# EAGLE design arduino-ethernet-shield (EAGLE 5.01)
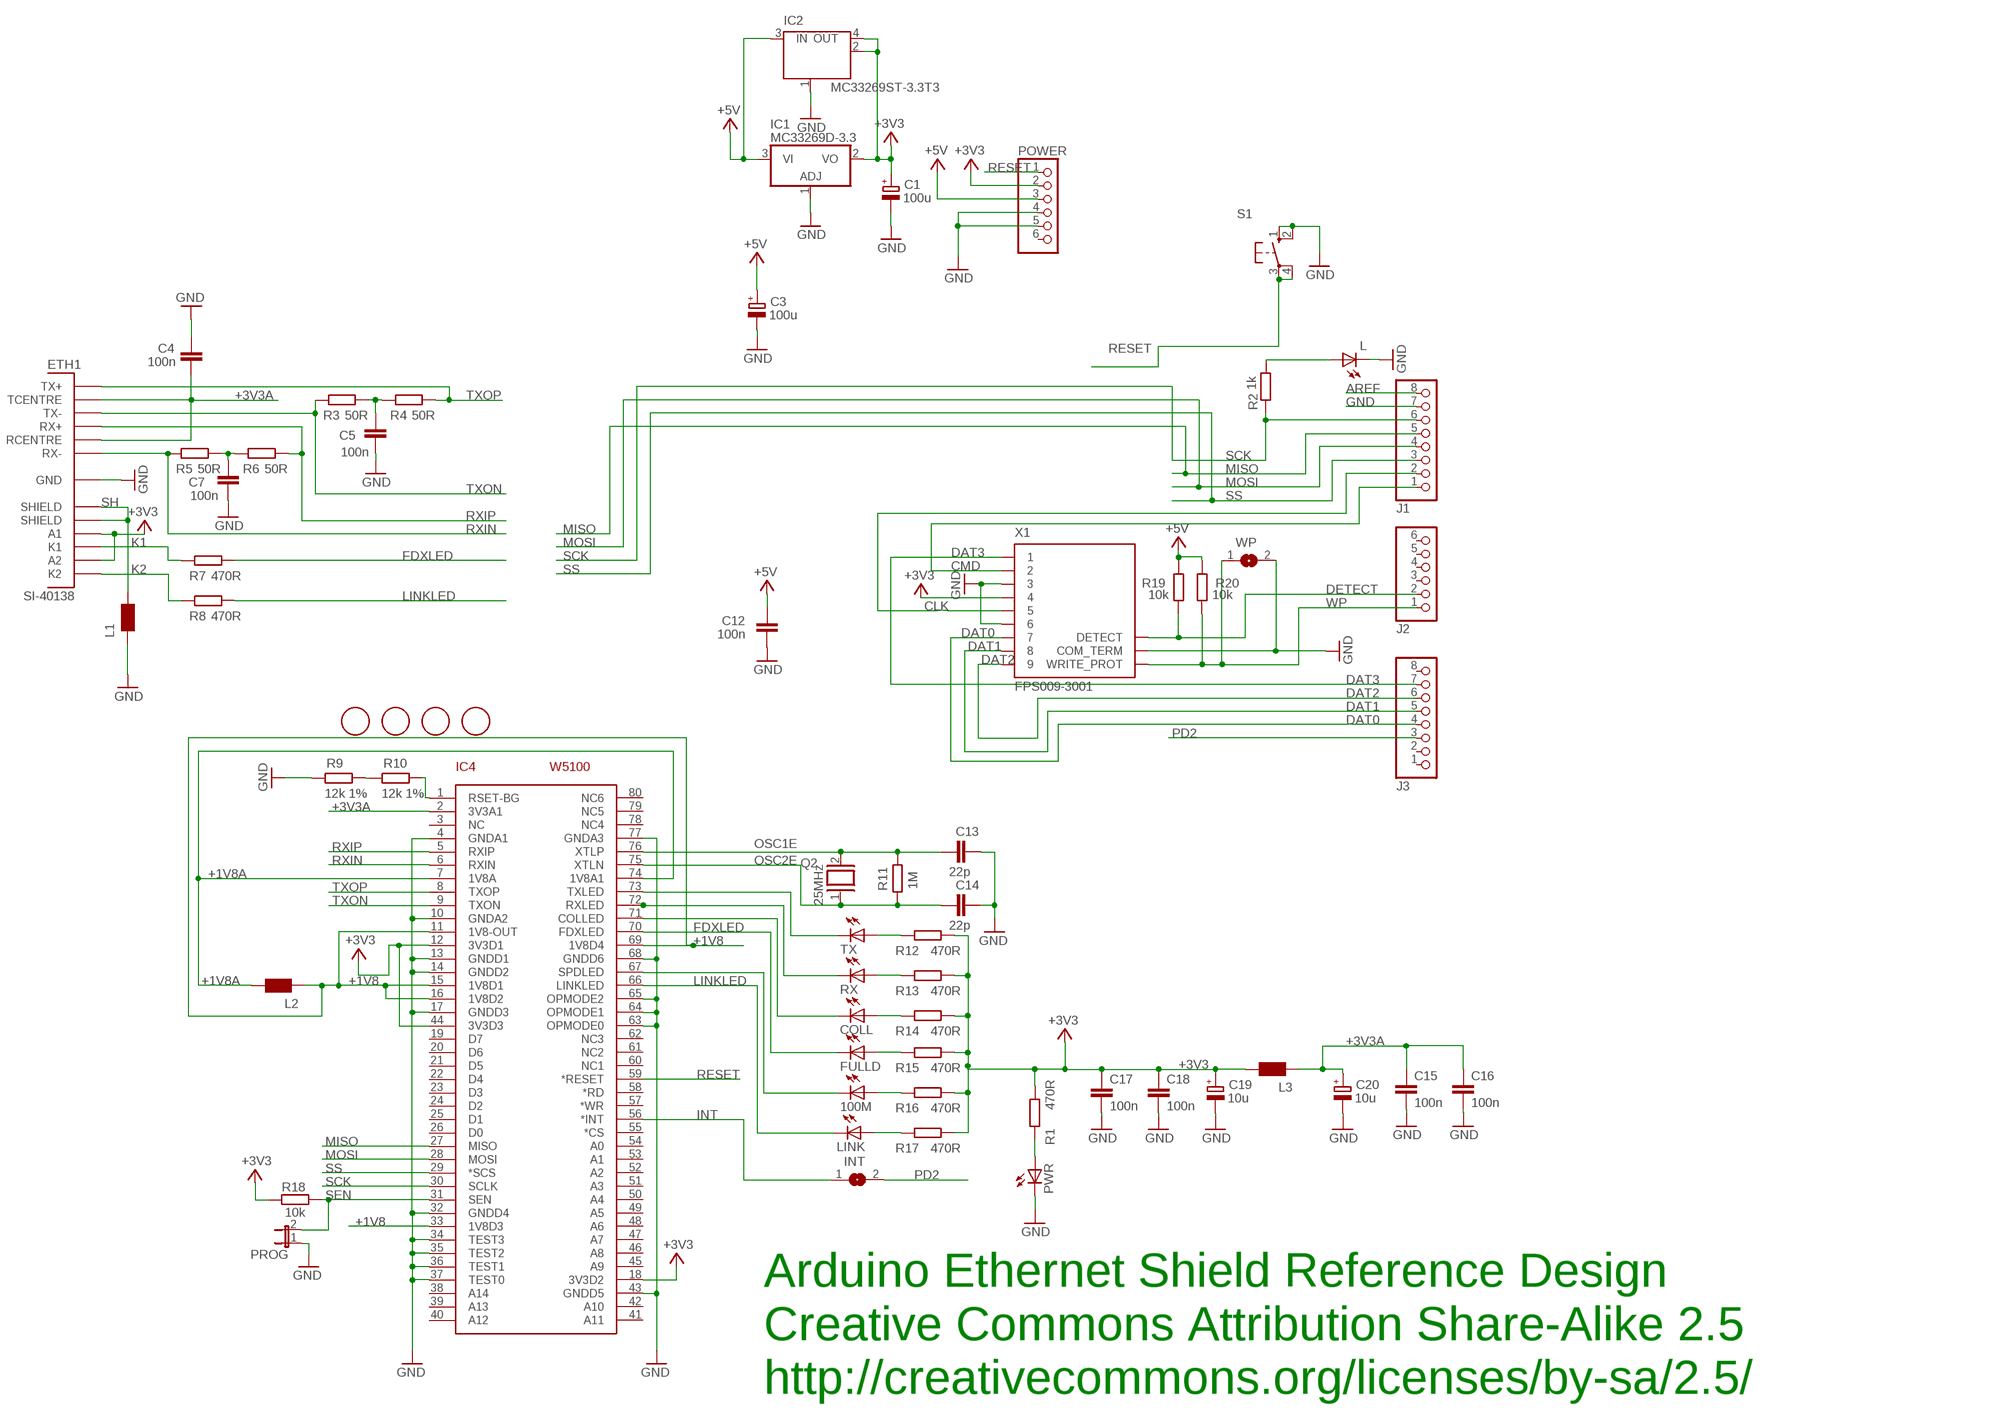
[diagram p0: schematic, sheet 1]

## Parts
100M  LEDCHIPLED_0805  [CHIPLED_0805]
C1  100u  CPOL-EUSMCD  [SMC_D]
C3  100u  CPOL-EUSMCD  [SMC_D]
C4  100n  C-EU  [0805RND]
C5  100n  C-EU  [0805RND]
C7  100n  C-EU  [0805RND]
C12  100n  C-EU  [0805RND]
C13  22p  C-EU  [0805RND]
C14  22p  C-EU  [0805RND]
C15  100n  C-EU  [0805RND]
C16  100n  C-EU  [0805RND]
C17  100n  C-EU  [0805RND]
C18  100n  C-EU  [0805RND]
C19  10u  CPOL-EUSMCB  [SMC_B]
C20  10u  CPOL-EUSMCB  [SMC_B]
COLL  LEDCHIPLED_0805  [CHIPLED_0805]
ETH1  SI-40138  [SI40138]
F1  FIDUCIALMOUNT  [FIDUCIA-MOUNT]
F2  FIDUCIALMOUNT  [FIDUCIA-MOUNT]
F3  FIDUCIALMOUNT  [FIDUCIA-MOUNT]
F4  FIDUCIALMOUNT  [FIDUCIA-MOUNT]
FULLD  LEDCHIPLED_0805  [CHIPLED_0805]
IC1  MC33269D-3.3  [DPACK]
IC2  MC33269ST-3.3T3  [SOT223]
IC4  W5100  [SQFP-S-10X10-80]
INT  SJ  [SJ]
J1  PINHD-1X8  [1X08]
J2  PINHD-1X6  [1X06]
J3  PINHD-1X8  [1X08]
L  LEDCHIPLED_0805  [CHIPLED_0805]
L1  WE-CBF_0805  [0805]
L2  WE-CBF_0805  [0805]
L3  WE-CBF_0805  [0805]
LINK  LEDCHIPLED_0805  [CHIPLED_0805]
POWER  PINHD-1X6  [1X06]
PROG  JP1E  [JP1]
PWR  LEDCHIPLED_0805  [CHIPLED_0805]
Q2  25MHz  XTAL/S  [QS]
R1  470R  R-EU_  [0805RND]
R2  1k  R-EU_  [0805RND]
R3  50R  R-EU_  [0805RND]
R4  50R  R-EU_  [0805RND]
R5  50R  R-EU_  [0805RND]
R6  50R  R-EU_  [0805RND]
R7  470R  R-EU_  [0805RND]
R8  470R  R-EU_  [0805RND]
R9  12k 1%  R-EU_  [0805RND]
R10  12k 1%  R-EU_  [0805RND]
R11  1M  R-EU_  [0805RND]
R12  470R  R-EU_  [0805RND]
R13  470R  R-EU_  [0805RND]
R14  470R  R-EU_  [0805RND]
R15  470R  R-EU_  [0805RND]
R16  470R  R-EU_  [0805RND]
R17  470R  R-EU_  [0805RND]
R18  10k  R-EU_  [0805RND]
R19  10k  R-EU_  [0805RND]
R20  10k  R-EU_  [0805RND]
RX  LEDCHIPLED_0805  [CHIPLED_0805]
S1  10-XX  [B3F-10XX]
TX  LEDCHIPLED_0805  [CHIPLED_0805]
WP  SJ  [SJ]
X1  FPS009-3001  [FPS009-3000]

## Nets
+1V8 [power]: IC4.11(1V8-OUT) IC4.15(1V8D1) IC4.16(1V8D2) IC4.33(1V8D3) IC4.69(1V8D4) L2.1
+1V8A [power]: IC4.7(1V8A) IC4.74(1V8A1) L2.2
+3V3 [power]: C1.+ C17.P$1 C18.P$1 C19.+ ETH1.9(A1) ETH1.11(A2) IC1.2(VO) IC2.2(OUT) IC2.4(OUT) IC4.12(3V3D1) IC4.18(3V3D2) IC4.44(3V3D3) L3.2 POWER.2 R1.P$1 R12.P$1 R13.P$1 R14.P$1 R15.P$1 R16.P$1 R17.P$1 R18.P$1 X1.4
+3V3A [power]: C4.P$1 C15.P$1 C16.P$1 C20.+ ETH1.2(TCENTRE) ETH1.5(RCENTRE) IC4.2(3V3A1) L3.1
+5V [power]: C3.+ C12.P$1 IC1.3(VI) IC2.3(IN) POWER.3 R19.P$2 R20.P$2
AREF: J1.8
CLK: J1.2 X1.5
CMD: J1.1 X1.2
DAT0: J3.4 X1.7
DAT1: J3.5 X1.8
DAT2: J3.6 X1.9
DAT3: J3.7 X1.1
DETECT: J2.2 R19.P$1 X1.DETECT
FDXLED: FULLD.C IC4.70(FDXLED) R7.P$1
GND [power]: C1.- C3.- C4.P$2 C5.P$1 C7.P$1 C12.P$2 C13.P$1 C14.P$1 C15.P$2 C16.P$2 C17.P$2 C18.P$2 C19.- C20.- ETH1.8(GND) IC1.1(ADJ) IC2.1(GND/ADJ) IC4.4(GNDA1) IC4.10(GNDA2) IC4.13(GNDD1) IC4.14(GNDD2) IC4.17(GNDD3) IC4.32(GNDD4) IC4.34(TEST3) IC4.35(TEST2) IC4.36(TEST1) IC4.37(TEST0) IC4.43(GNDD5) IC4.63(OPMODE0) IC4.64(OPMODE1) IC4.65(OPMODE2) IC4.68(GNDD6) IC4.77(GNDA3) J1.7 L1.1 L.C POWER.4 POWER.5 PROG.1 PWR.C R9.P$2 S1.1(S) S1.2(S1) WP.2 X1.3 X1.6 X1.COM_TERM
INT: IC4.56(*INT) INT.1
K1: ETH1.10(K1) R7.P$2
K2: ETH1.12(K2) R8.P$2
LINKLED: IC4.66(LINKLED) LINK.C R8.P$1
MISO: IC4.27(MISO) J1.5
MOSI: IC4.28(MOSI) J1.4
N$1: PWR.A R1.P$2
N$2: L.A R2.P$1
N$5: 100M.C IC4.67(SPDLED)
N$6: IC4.73(TXLED) TX.C
N$7: IC4.72(RXLED) RX.C
N$8: COLL.C IC4.71(COLLED)
N$9: R12.P$2 TX.A
N$10: C5.P$2 R3.P$1 R4.P$2
N$22: R13.P$2 RX.A
N$23: COLL.A R14.P$2
N$24: FULLD.A R15.P$2
N$25: 100M.A R16.P$2
N$26: LINK.A R17.P$2
N$29: C7.P$2 R5.P$1 R6.P$2
N$30: R9.P$1 R10.P$2
N$31: IC4.1(RSET-BG) R10.P$1
OSC1E: C13.P$2 IC4.76(XTLP) Q2.2 R11.P$1
OSC2E: C14.P$2 IC4.75(XTLN) Q2.1 R11.P$2
PD2: INT.2 J3.3
RESET: IC4.59(*RESET) POWER.1 S1.3(P) S1.4(P1)
RXIN: ETH1.6(RX-) IC4.6(RXIN) R5.P$2
RXIP: ETH1.4(RX+) IC4.5(RXIP) R6.P$1
SCK: IC4.30(SCLK) J1.6 R2.P$2
SEN: IC4.31(SEN) PROG.2 R18.P$2
SH: ETH1.S1(SHIELD) ETH1.S2(SHIELD) L1.2
SS: IC4.29(*SCS) J1.3
TXON: ETH1.3(TX-) IC4.9(TXON) R3.P$2
TXOP: ETH1.1(TX+) IC4.8(TXOP) R4.P$1
WP: J2.1 R20.P$1 WP.1 X1.WRITE_PROT
Unconnected: IC4.3(NC) IC4.19(D7) IC4.20(D6) IC4.21(D5) IC4.22(D4) IC4.23(D3) IC4.24(D2) IC4.25(D1) IC4.26(D0) IC4.38(A14) IC4.39(A13) IC4.40(A12) IC4.41(A11) IC4.42(A10) IC4.45(A9) IC4.46(A8) IC4.47(A7) IC4.48(A6) IC4.49(A5) IC4.50(A4) IC4.51(A3) IC4.52(A2) IC4.53(A1) IC4.54(A0) IC4.55(*CS) IC4.57(*WR) IC4.58(*RD) IC4.60(NC1) IC4.61(NC2) IC4.62(NC3) IC4.78(NC4) IC4.79(NC5) IC4.80(NC6) J2.3 J2.4 J2.5 J2.6 J3.1 J3.2 J3.8 POWER.6

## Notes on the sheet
- Arduino Ethernet Shield Reference Design
- Creative Commons Attribution Share-Alike 2.5
- http://creativecommons.org/licenses/by-sa/2.5/

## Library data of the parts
100M COLL FULLD L LINK PWR RX TX = led:LED: LED
C1 C3 C19 C20 = rcl:CPOL-EU: POLARIZED CAPACITOR, European symbol
C4 C5 C7 C12-C18 = rcl:C-EU: CAPACITOR, European symbol
ETH1 = ethernet:SI-40138: Ethernet Jack with Integrated Magnetics The Belfuse SI-10021 (Rapid order code 24-0484) is a single RJ-45 jack with integrated magnetics, suitable for Ethernet use.
F1-F4 = SmartPrj:FIDUCIALMOUNT
IC1 = linear:MC33269?*: Adjustable Output Low Dropout Voltage Regulator 800 mA Source: http://www.onsemi.com/pub/Collateral/MC33269-D.PDF
IC2 = linear:MC33269ST*: Adjustable Output Low Dropout Voltage Regulator 800 mA Source: http://www.onsemi.com/pub/Collateral/MC33269-D.PDF
IC4 = SmartPrj:W5100
INT WP = jumper:SJ: SMD solder JUMPER
J1 J3 = pinhead:PINHD-1X8: PIN HEADER
J2 POWER = pinhead:PINHD-1X6: PIN HEADER
L1-L3 = wuerth-elektronik:WE-CBF: SMD EMI Suppression Ferrite Beads
PROG = jumper:JP1E: JUMPER
Q2 = special:XTAL/S: CRYSTAL
R1-R20 = rcl:R-EU_: RESISTOR, European symbol
S1 = switch-omron:10-XX: OMRON SWITCH
X1 = con-yamaichi:FPS009-300*: SD Card and MMC Reader (Manual Insertion) Source: http://www.yamaichi.de/pdf/c_fps009_3000.pdf

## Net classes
0 default: width 0.152 mm, drill 0.61 mm, clearance 0.152 mm
1 power: width 0.152 mm, drill 0.61 mm, clearance 0.152 mm
2 VIN: width 0.61 mm, drill 0.813 mm

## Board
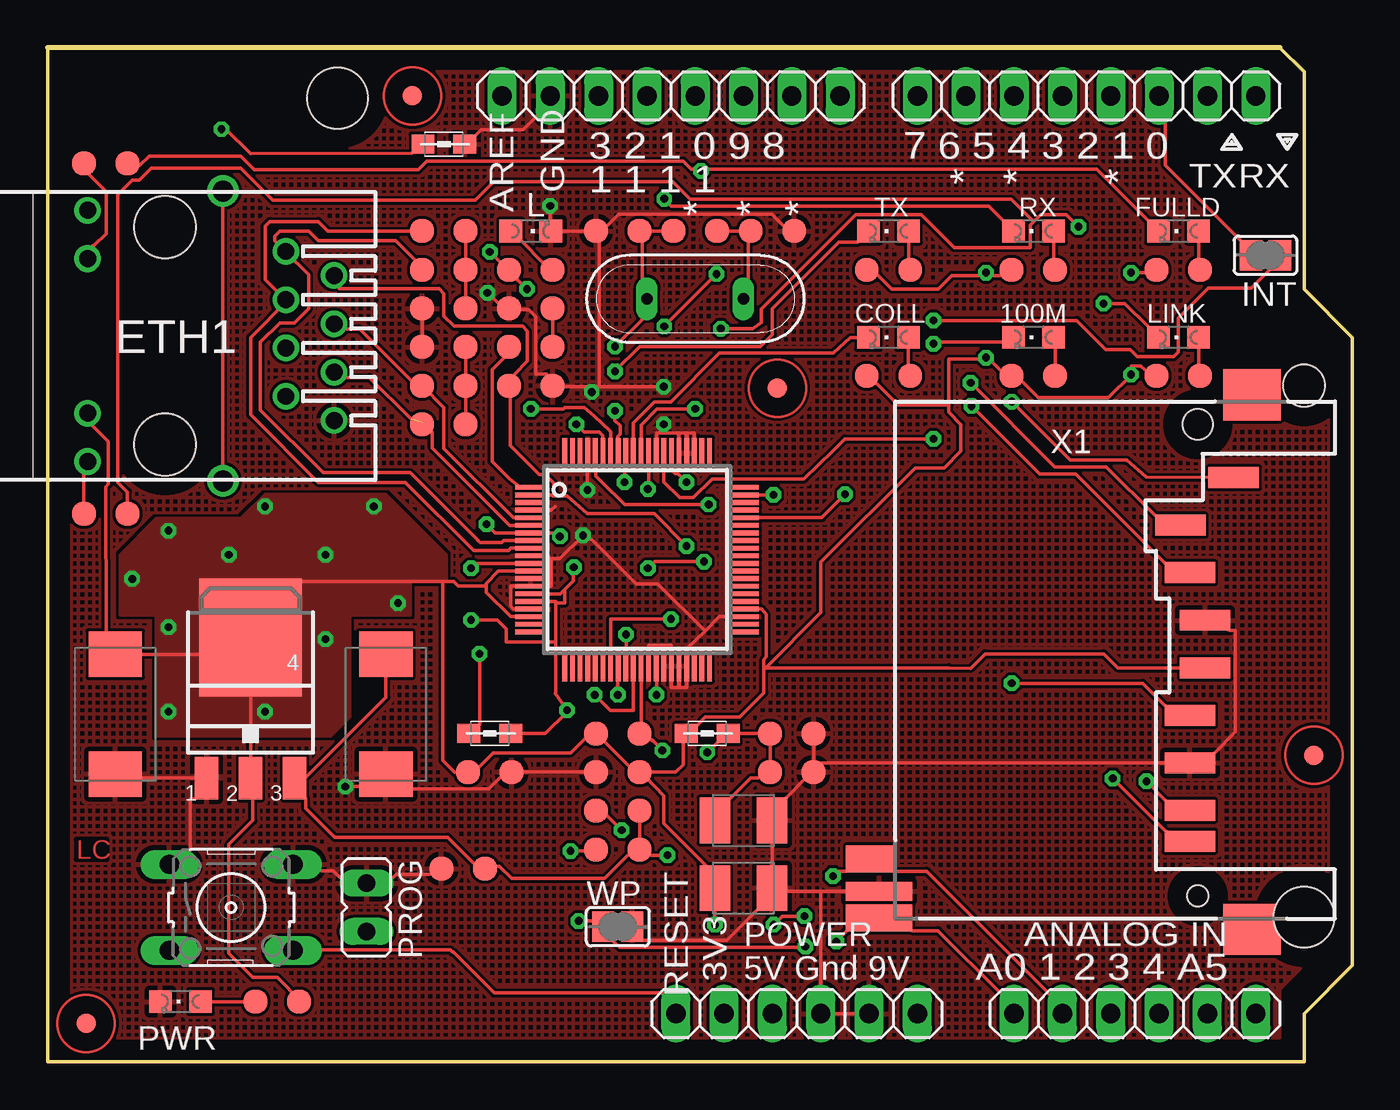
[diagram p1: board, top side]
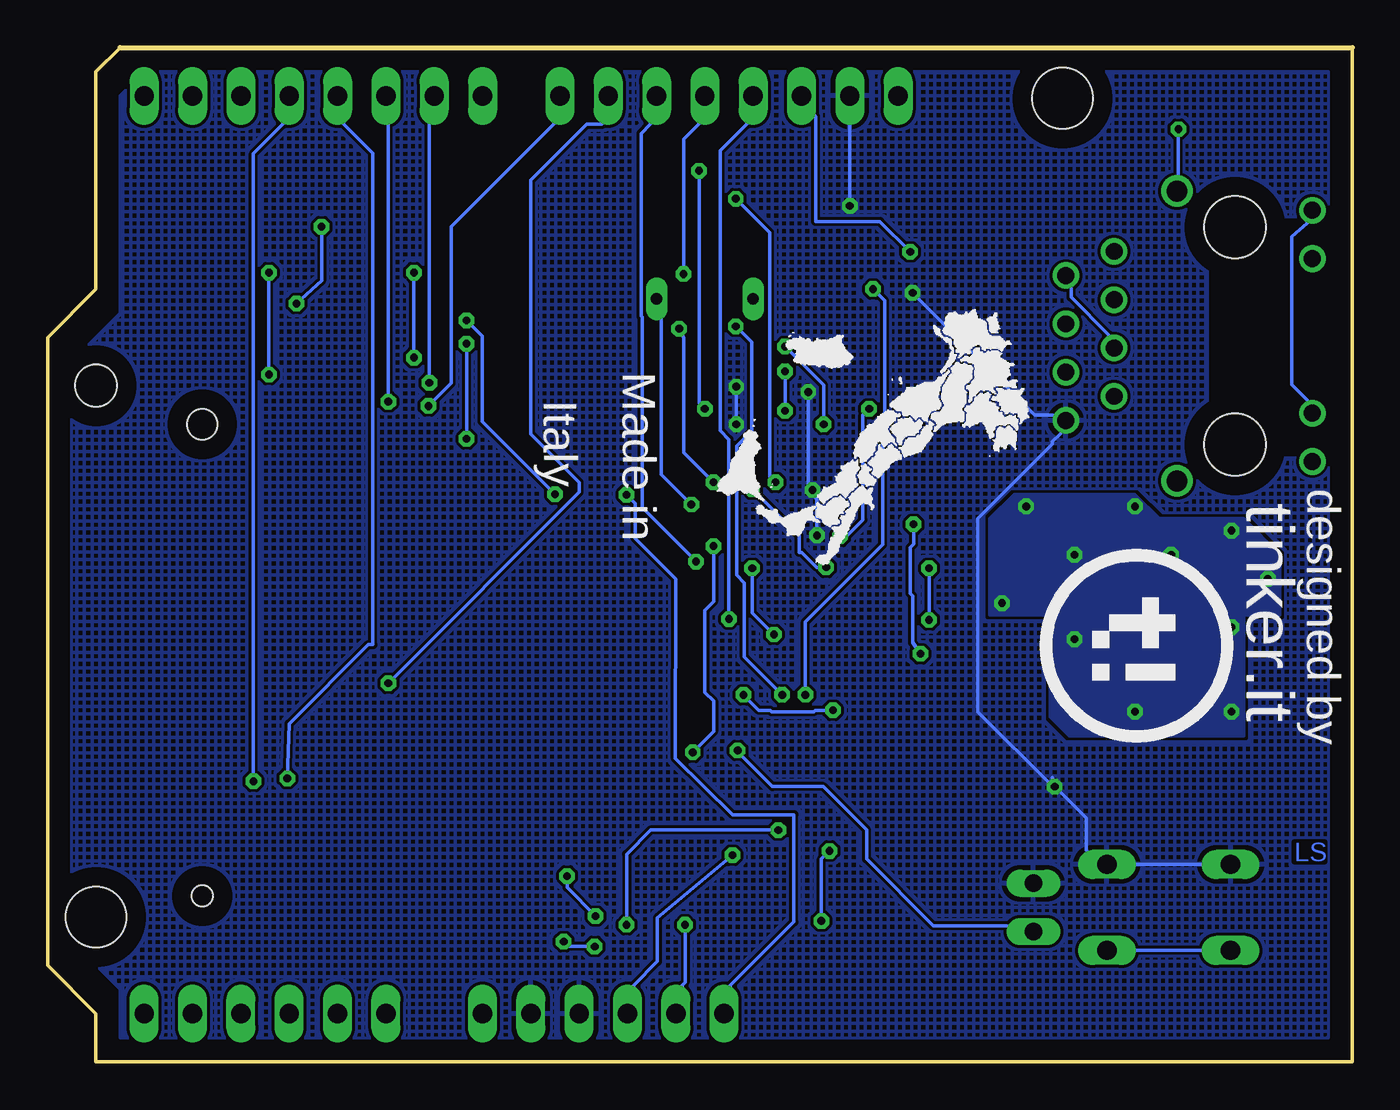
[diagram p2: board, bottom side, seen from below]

Size 68.58 x 53.34 mm. Coordinates in mm from the lower left corner, seen from the top.
Outline: 0,53.34 0,0 66.04,0 66.04,2.54 68.58,5.08 68.58,38.1 66.04,40.64 66.04,52.07 64.77,53.34 0,53.34
Copper layers (1*16): Top 0.035mm / dielectric 1.5mm / Bottom 0.035mm
Design rules "default *": minimum track width 8mil, minimum drill 20mil, track to track 6mil, track to pad 6mil, pad to pad 5mil, via to via 8mil, smd to smd 6mil, copper to edge 40mil, drill to drill 10mil, minimum pad ring 10mil, minimum via ring 8mil, stop-mask expansion 4mil, vias tented up to drill 0mil, thermal gap 10mil
Holes 2.2 mm at 66.04,35.56
Holes 3.2 mm at 66.04,7.62 15.24,50.67

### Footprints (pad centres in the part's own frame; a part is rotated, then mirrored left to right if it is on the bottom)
CHIPLED_0805 = smd 1.2 x 1.2: A 0,-1.05; C 0,1.05
SMC_D = smd 2.4 x 2.8: + -3.15,0; - 3.15,0
0805RND = smd 1.27 x 1.27: P$1 -1.143,0; P$2 1.143,0
SMC_B = smd 1.6 x 2.4: + -1.5,0; - 1.5,0
SI40138 = drill 0.889 round: 1 -4.445,6.35; 2 -3.175,8.89; 3 -1.905,6.35; 4 -0.635,8.89; 5 0.635,6.35; 6 1.905,8.89; 7 3.175,6.35; 8 4.445,8.89; 9 -6.604,-4.064; 10 -4.064,-4.064; 11 4.064,-4.064; 12 6.604,-4.064 | drill 1.1 round: S1 -7.62,3.048; S2 7.62,3.048 | hole 3.251: -5.715,0; 5.715,0
FIDUCIA-MOUNT = smd 1.016 x 1.016: P$1 0,0
DPACK = smd 1 x 1.6: 1 -2.28,-4.8; 3 2.28,-4.8 | smd 5.4 x 6.2: 2 0,2.5
SOT223 = smd 1.219 x 2.235: 1 -2.311,-3.099; 2 0,-3.099; 3 2.311,-3.099 | smd 3.6 x 2.2: 4 0,3.099
SQFP-S-10X10-80 = smd 0.25 x 1.6: 1 -3.8,-5.6; 2 -3.4,-5.6; 3 -3,-5.6; 4 -2.6,-5.6; 5 -2.2,-5.6; 6 -1.8,-5.6; 7 -1.4,-5.6; 8 -1,-5.6; 9 -0.6,-5.6; 10 -0.2,-5.6; 11 0.2,-5.6; 12 0.6,-5.6; 13 1,-5.6; 14 1.4,-5.6; 15 1.8,-5.6; 16 2.2,-5.6; 17 2.6,-5.6; 18 3,-5.6; 19 3.4,-5.6; 20 3.8,-5.6; 41 3.8,5.6; 42 3.4,5.6; 43 3,5.6; 44 2.6,5.6; 45 2.2,5.6; 46 1.8,5.6; 47 1.4,5.6; 48 1,5.6; 49 0.6,5.6; 50 0.2,5.6; 51 -0.2,5.6; 52 -0.6,5.6; 53 -1,5.6; 54 -1.4,5.6; 55 -1.8,5.6; 56 -2.2,5.6; 57 -2.6,5.6; 58 -3,5.6; 59 -3.4,5.6; 60 -3.8,5.6 | smd 1.6 x 0.25: 21 5.6,-3.8; 22 5.6,-3.4; 23 5.6,-3; 24 5.6,-2.6; 25 5.6,-2.2; 26 5.6,-1.8; 27 5.6,-1.4; 28 5.6,-1; 29 5.6,-0.6; 30 5.6,-0.2; 31 5.6,0.2; 32 5.6,0.6; 33 5.6,1; 34 5.6,1.4; 35 5.6,1.8; 36 5.6,2.2; 37 5.6,2.6; 38 5.6,3; 39 5.6,3.4; 40 5.6,3.8; 61 -5.6,3.8; 62 -5.6,3.4; 63 -5.6,3; 64 -5.6,2.6; 65 -5.6,2.2; 66 -5.6,1.8; 67 -5.6,1.4; 68 -5.6,1; 69 -5.6,0.6; 70 -5.6,0.2; 71 -5.6,-0.2; 72 -5.6,-0.6; 73 -5.6,-1; 74 -5.6,-1.4; 75 -5.6,-1.8; 76 -5.6,-2.2; 77 -5.6,-2.6; 78 -5.6,-3; 79 -5.6,-3.4; 80 -5.6,-3.8
SJ = smd 1.168 x 1.6: 1 -0.762,0; 2 0.762,0
1X08 = drill 1.016 long: 1 -8.89,0; 2 -6.35,0; 3 -3.81,0; 4 -1.27,0; 5 1.27,0; 6 3.81,0; 7 6.35,0; 8 8.89,0
1X06 = drill 1.016 long: 1 -6.35,0; 2 -3.81,0; 3 -1.27,0; 4 1.27,0; 5 3.81,0; 6 6.35,0
0805 = smd 1.2 x 1: 1 -1.1,0; 2 1.1,0
JP1 = drill 0.914 long: 1 0,-1.27; 2 0,1.27
QS = drill 0.61 long: 1 -2.54,0; 2 2.54,0
B3F-10XX = drill 1.016 long: 1 -3.251,2.261; 2 3.251,2.261; 3 -3.251,-2.261; 4 3.251,-2.261
FPS009-3000 = smd 2.65 x 1.1: 1 -0.915,-5.3; 2 -0.415,-7.8; 3 0.385,-10.3; 4 0.385,-12.8; 5 -0.415,-15.3; 6 -0.415,-17.8; 7 -0.415,-20.3; 8 -0.415,-21.925; 9 1.885,-2.8 | smd 3.5 x 1: COM_TERM -16.75,-24.55 | smd 2.5 x 1.4: DETECT -17.25,-22.85 | smd 3 x 2.7: M1 2.85,1.55; M2 2.85,-26.55 | smd 3.5 x 1.4: WRITE_PROT -16.75,-25.95 | hole 1.6: 0,0 | hole 1.1: 0,-24.8

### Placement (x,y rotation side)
100M  51.82,38.1 90 top
C1  3.56,18.29 270 top
C3  17.78,18.29 270 top
C4  25.4,35.56 0 top
C5  20.83,39.62 0 top
C7  20.83,37.59 0 top
C12  21.84,10.16 180 top
C13  38.1,43.69 180 top
C14  29.97,43.69 0 top
C15  39.12,15.24 0 top
C16  39.12,17.27 0 top
C17  23.24,15.24 0 top
C18  29.97,15.24 180 top
C19  36.58,9.14 0 top
C20  36.58,12.7 0 top
COLL  44.2,38.1 90 top
ETH1  6.17,38.17 270 top
F1  38.35,35.43 0 top
F2  66.55,16.13 0 top
F3  19.18,50.8 0 top
F4  2.03,2.03 0 top
FULLD  59.44,43.69 90 top
IC1  10.67,19.81 0 top
IC2  10.67,18.03 0 top
IC4  30.99,26.42 270 top
INT  64.01,42.42 180 top
J1  32.77,50.8 180 top
J2  57.15,2.54 0 top
J3  54.61,50.8 180 top
L  25.4,43.69 270 top
L1  20.83,48.26 180 top
L2  23.24,17.27 180 top
L3  34.67,17.27 180 top
LINK  59.44,38.1 90 top
POWER  39.37,2.54 0 top
PROG  16.76,8.13 180 top
PWR  6.99,3.17 90 top
Q2  34.04,40.13 0 top
R1  12.06,3.17 180 top
R2  25.4,41.66 180 top
R3  20.83,43.69 180 top
R4  20.83,41.66 0 top
R5  20.83,33.53 180 top
R6  20.83,35.56 0 top
R7  3.05,47.24 180 top
R8  3.05,28.83 180 top
R9  25.4,39.62 180 top
R10  25.4,37.59 0 top
R11  34.04,43.69 180 top
R12  44.2,41.66 0 top
R13  51.82,41.66 0 top
R14  44.2,36.07 0 top
R15  59.44,41.66 0 top
R16  51.82,36.07 0 top
R17  59.44,36.07 0 top
R18  29.97,17.27 0 top
R19  29.97,13.21 0 top
R20  29.97,11.18 0 top
RX  51.82,43.69 90 top
S1  9.65,8.13 0 top
TX  44.2,43.69 90 top
WP  29.97,7.11 0 top
X1  60.45,33.53 0 top

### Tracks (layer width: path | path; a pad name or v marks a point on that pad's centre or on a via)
+1V8  (via drill 0.41)
  Top 0.178: 26.72,22.1 26.72,24.13 | 26.72,24.13 26.72,24.21 26.19,24.21 IC4.16 | 26.72,22.1 26.72,19.43 26.67,19.38 v27.3,18.49 27.3,18.41 26.16,17.27 L2.1 | v22.25,25.96 22.5,26.21 24.49,26.21 IC4.11 | v22.25,23.24 23.62,23.24 24.11,22.76 24.11,22.1 26.72,22.1 | v32,19.3 32,20.04 IC4.33 | v31.55,30.12 31.57,30.12 31.6,30.5 IC4.69 | 27.14,24.8 26.95,24.61 26.77,24.61 26.19,24.61 IC4.15 | 27.14,24.8 27.64,25.3 v27.66,26.01 | 26.72,24.13 27.18,24.13 27.18,24.77 27.14,24.8
  Bottom 0.178: v22.25,23.24 v22.25,25.96 | v32,19.3 31.19,18.49 30.61,18.49 30.53,18.41 28.32,18.41 28.25,18.49 v27.3,18.49 | v31.55,30.12 29.08,27.66 29.08,26.8 28.93,26.8 28.14,26.01 v27.66,26.01
+1V8A  (via drill 0.41)
  Top 0.178: v22.71,21.46 22.71,17.75 L2.2 | v23.06,28.27 23.52,27.81 24.61,27.81 IC4.7 26.19,27.81 26.75,27.81 v26.92,27.64 | v25.4,34.34 27.1,34.34 27.18,34.42 28.19,34.42 28.73,33.96 29.57,33.16 29.59,33.09 29.59,33.05 IC4.74
  Bottom 0.178: v22.71,21.46 23.11,22.05 23.11,24.51 23.24,24.64 23.24,27.05 23.06,27.23 v23.06,28.27 | v25.4,34.34 25.73,34.01 25.73,28.5 26.59,27.64 v26.92,27.64
+3V3  (via drill 0.41)
  Top 0.178: R18.P$1 28.22,16.97 27.51,16.26 23.42,16.26 22.71,15.54 C17.P$1 21.41,15.21 20.78,15.85 20.78,25.27 | 23.06,25.02 23.06,24.69 24.33,23.42 24.61,23.42 IC4.18 | 23.06,25.02 23.06,25.17 23.7,25.81 24.66,25.81 IC4.12 | IC2.4 IC2.2 10.79,14.94 10.79,12.7 9.53,11.43 9.53,5.71 10.79,4.45 12.06,4.45 13.34,3.17 R1.P$1 | IC2.4 IC1.2 | IC1.2 7.98,21.44 4.95,21.44 C1.+ 3.07,22.63 3.05,30.23 3.2,30.38 3.2,32.61 2.39,33.43 ETH1.11 | 20.78,25.27 13.36,25.27 IC1.2 | 20.78,25.27 21.34,25.27 21.59,25.02 23.06,25.02 | IC2.4 | IC2.4 IC1.2 | 49.33,41.35 50.06,41.35 R13.P$1 | 49.33,41.35 47.52,41.35 46.81,40.64 44.37,40.64 43.66,41.35 R12.P$1 | 49.33,36.96 49.48,36.96 50.06,36.37 R16.P$1 50.93,36.07 52.07,34.92 55.75,34.92 56.95,36.12 v56.95,36.14 56.95,36.6 57.45,36.6 57.68,36.37 R17.P$1 | 49.33,36.96 47.37,36.96 47.37,34.54 | v56.95,41.5 57.68,41.5 R15.P$1 | v49.33,41.5 49.33,41.35 | 49.33,36.96 v49.33,37.03 | 37.64,20.73 37.64,21.13 37.77,21.31 37.77,23.52 37.54,23.81 37.41,23.81 IC4.44 | 37.64,20.73 37.64,19.41 36.37,18.14 34.57,18.14 34.16,17.73 L3.2 33.57,17.19 33.4,17.02 33.4,15.62 33.02,15.24 C18.P$1 | C18.P$1 31.42,15.01 32.38,13.99 32.38,12.55 34.59,10.34 34.59,9.47 34.8,9.27 C19.+ 35.08,7.95 v35.08,7.21 | X1.4 59.51,20.73 56.24,20.73 55.5,21.46 49.28,21.46 48.51,20.7 47.37,20.73 37.71,20.73 | 37.64,20.73 37.71,20.73 | 47.37,34.54 47.37,34.16 48.01,33.53 48.01,32.13 47.12,31.24 45.59,31.24 40.64,26.29 40.64,23.64 37.71,20.7 37.71,20.73 | R14.P$1 43.18,36.07 44.7,34.54 47.37,34.54 | R18.P$1 28.57,17.53 | C18.P$1 30.86,15.24 R18.P$1
  Bottom 0.178: ETH1.11 2.39,34.8 3.2,35.61 3.2,43.41 2.39,44.09 ETH1.9 | v56.95,36.14 v56.95,41.5 | v49.33,37.03 v49.33,41.5 | v35.08,7.21 35.08,4.19 35.23,4.04 POWER.2
  other vias: 6.35,27.94 11.43,29.21 17.14,29.21 18.41,24.13 14.61,22.23 11.43,18.41 6.35,18.41 6.35,22.86 4.45,25.4 9.53,26.67 14.61,26.67
  pour Top (isolate 0.152, no thermals): 5.71,17.14 14.88,17.14 15.88,18.14 15.88,23.5 19.05,23.5 19.05,25.4 20.95,25.4 20.95,26.67 17.78,29.84 11.43,29.84 10.16,28.57 5.71,28.57 3.81,26.67 3.81,23.5 5.71,23.5
  pour Bottom (isolate 0.152, no thermals): 5.71,17.14 14.88,17.14 15.88,18.14 15.88,23.5 19.05,23.5 19.05,28.57 17.78,29.84 11.43,29.84 10.16,28.57 5.71,28.57 3.81,26.67 3.81,23.5 5.71,23.5
+3V3A  (via drill 0.41)
  Top 0.178: C20.+ 35.87,13.84 36.96,14.94 37.36,14.94 C15.P$1 C16.P$1 L3.1 35.2,16.79 34.7,16.28 v34.67,16.28 | 26.59,29.82 26.59,30.43 26.14,30.89 25.83,30.89 24.31,32.41 24.31,34.95 C4.P$1 24.56,36.17 25.22,36.85 25.22,38.43 24.97,38.68 21.36,38.68 20.83,39.22 20.83,40.41 20.57,40.66 15.34,40.66 ETH1.2 | 26.59,29.82 26.19,29.82 IC4.2 | v33.58,27.13 31.88,28.83 28.37,28.83 27.3,29.77 26.54,29.77 26.59,29.82
  Bottom 0.178: ETH1.5 12.8,38.23 14.78,40.21 14.78,40.66 ETH1.2 | v34.67,16.28 33.58,17.37 33.58,18.97 34.04,19.43 34.04,23.75 33.58,24.21 v33.58,27.13
+5V  (via drill 0.41)
  Top 0.178: R20.P$2 30.5,10.87 29.29,9.65 24.38,9.65 23.75,10.29 23.6,10.29 C12.P$1 22.38,10.46 21.03,11.81 15.09,11.81 13.56,13.34 13.56,13.84 IC2.3 IC1.3 13.11,15.01 13.59,14.99 17.78,19.18 C3.+ | R20.P$2 R19.P$2 | v32.59,10.87 31.73,10.87 R20.P$2
  Bottom 0.178: v32.59,10.87 36.52,7.57 36.52,5.28 37.77,4.04 POWER.3
CLK  (via drill 0.41)
  Top 0.178: v50.67,19.91 57.56,19.91 58.73,18.75 X1.5
  Bottom 0.178: v50.67,19.91 40.64,29.96 40.64,30.48 43.18,33.02 43.18,46.35 40.23,49.3 39.45,49.3 J1.2
CMD  (via drill 0.41)
  Top 0.178: v48.56,34.49 52.15,30.91 54.05,30.91 58.73,26.24 X1.2
  Bottom 0.178: v48.56,34.49 47.37,35.69 47.37,43.92 41.99,49.3 J1.1
DAT0  (via drill 0.41)
  Top 0.178: v57.76,14.76 58.75,13.77 X1.7
  Bottom 0.178: v57.76,14.76 57.76,47.75 56.21,49.3 J3.4
DAT1  (via drill 0.41)
  Top 0.178: v55.98,14.91 58.75,12.14 X1.8
  Bottom 0.178: v55.98,14.91 55.88,17.78 51.71,21.95 51.49,21.95 51.49,47.78 53.01,49.3 J3.5
DAT2  (via drill 0.41)
  Top 0.178: v50.67,34.72 53.75,31.65 56.72,31.65 57.73,30.76 X1.9
  Bottom 0.178: v50.67,34.72 50.67,49.3 J3.6
DAT3  (via drill 0.41)
  Top 0.178: v48.51,35.71 52.93,31.29 55.65,31.29 58.22,28.73 X1.1
  Bottom 0.178: v48.51,35.71 48.51,49.3 J3.7
DETECT  (via drill 0.41)
  Top 0.178: v30.18,12.19 30.15,12.19 29.44,12.9 R19.P$1 | v38.15,7.21 38.61,7.67 v39.78,7.67 | v41.27,9.78 41.53,10.03 41.96,10.03 X1.DETECT 44.45,10.03 46.2,10.03 52.6,3.63 J2.2
  Bottom 0.178: v30.18,12.19 36.88,12.19 38.15,10.92 v38.15,7.21 | v39.78,7.67 41.27,9.17 v41.27,9.78
FDXLED  (via drill 0.41)
  Top 0.178: 34.34,46.94 33.83,46.94 33.4,47.37 19.94,47.37 19.47,46.91 10.87,46.91 10.16,47.62 5.33,47.62 4.83,47.12 4.55,47.07 R7.P$1 | 34.34,46.94 55.14,46.94 57.81,44.27 FULLD.C | v34.04,34.34 32.03,34.34 31.19,33.5 31.19,32.79 IC4.70 | 34.34,46.94 v34.34,46.86
  Bottom 0.178: v34.04,34.34 34.34,34.65 v34.34,46.86
GND  (via drill 0.41)
  Top 0.178: 32.41,21.89 31.6,21.89 31.6,21.61 IC4.32 | 32.41,21.89 IC4.34 | 32.41,21.89 32.79,21.89 IC4.35 32.77,19.68 33.2,19.68 IC4.36 33.17,19.68 33.6,19.68 IC4.37 33.6,21.74 34.56,22.67 | 34.56,22.67 35.31,23.42 35.79,23.42 IC4.43 | IC4.17 24.61,23.82 24.49,23.82 24.33,23.98 24.33,25.02 24.61,25.02 IC4.14 26.47,25.02 26.47,25.43 | 26.47,25.43 IC4.13 26.19,25.43 26.47,25.43 | 26.47,26.42 26.26,26.62 26.19,26.62 IC4.10 | 26.47,26.42 26.47,25.43 | v28.37,30.07 28.37,31.22 IC4.77 | 26.47,26.42 26.54,26.47 26.92,26.47 v28.14,27.69 28.63,27.46 30.94,25.15 32.08,25.15 34.56,22.67 | 32.38,33.07 32,33.07 32,32.79 IC4.68 | 32.38,33.07 33.17,33.07 | 33.17,33.07 IC4.65 | 33.17,33.07 33.58,33.07 IC4.64 33.63,33.07 33.98,33.07 IC4.63 | 28.6,35.51 27.15,35.51 C4.P$2 26.24,36.17 25.65,36.17 25.65,39.19 25.3,39.55 24.89,39.55 24.74,39.57 R9.P$2 23.65,39.93 23.14,40.44 v23.11,40.44 | 28.6,35.51 29.01,35.51 | 29.01,35.51 v32.38,35.51 | v32.38,33.53 32.38,33.07 | L1.1 22.5,48.74 22.78,49.02 24.99,49.02 25.68,49.71 J1.7 | C14.P$1 L.C 26.42,44.27 v26.42,45.01 | C13.P$1 38.63,43.99 38.05,44.58 30.02,44.58 29.44,43.99 C14.P$1 | 29.01,35.51 29.01,43.08 C14.P$1 | 28.6,35.51 v28.6,35.23 | X1.3 62.13,22.68 62.43,22.68 62.43,17.35 61.34,16.26 X1.6 58.73,15.72 40.69,15.72 C15.P$2 | POWER.5 POWER.4 40.64,8.97 | C15.P$2 C16.P$2 | C15.P$2 39.75,14.83 38.81,13.89 C20.- 38.08,11.51 38.08,10.34 C19.- | 40.64,8.97 38.86,8.97 C19.- | 40.64,8.97 41.96,8.97 X1.COM_TERM | C7.P$1 C5.P$1 | C18.P$2 C17.P$2 23.77,14.94 23.19,14.35 19.18,14.35 C3.- 16.38,14.48 v15.65,14.48 | IC1.1 IC2.1 | IC2.1 4.95,14.94 C1.- | S1.1 7.49,11.12 7.49,13.84 7.77,13.84 IC2.1
  Top 0.178: S1.2 14.4,10.06 15.01,10.06 15.37,9.7 PROG.1 18.16,9.7 18.31,9.86 20.09,9.86 C12.P$2 | C19.- 37.29,8 35.69,6.4 31.29,6.4 WP.2 | IC4.4 26.48,29.02 26.67,29.21
  Bottom 0.178: v28.14,27.69 28.14,29.54 v28.37,30.07 28.6,30.25 v28.6,35.23 | v32.38,35.51 v32.38,33.53 | v26.42,45.01 J1.7 | v15.65,14.48 13.99,12.83 13.99,11.12 S1.2 13.34,10.39 | v15.65,14.48 15.77,14.96 | v23.11,40.44 16.69,34.01 15.75,34.01 ETH1.8 15.34,33.05 15.77,32.61 15.77,32.49 19.68,28.57 19.68,18.41 15.75,14.48 v15.65,14.48 | S1.1 13.34,10.39 | 13.34,10.39 13.34,10.16
  pour Top (isolate 0.152, rank 2, hatched): 1.27,52.07 63.5,52.07 64.77,50.8 64.77,39.37 67.31,36.83 67.31,6.35 64.77,3.81 64.77,1.27 1.27,1.27 1.27,31.75 7.62,31.75 7.62,44.45 1.27,44.45
  pour Bottom (isolate 0.152, rank 2, hatched): 1.27,52.07 63.5,52.07 64.77,50.8 64.77,39.37 67.31,36.83 67.31,6.35 64.77,3.81 64.77,1.27 1.27,1.27 1.27,31.75 7.62,31.75 7.62,44.45 1.27,44.45
INT  (via drill 0.41)
  Top 0.178: v41.91,29.84 40.69,28.63 37.36,28.63 IC4.56 | INT.1 64.21,41.63 63.27,40.69 61.01,40.69 59.44,39.12 59.44,37.34 59.18,37.08 57.28,37.08 56.9,37.47 55.63,37.47 54.1,38.99 v46.56,38.99
  Bottom 0.178: v41.91,29.84 45.74,33.68 45.74,38.18 v46.56,38.99
K1
  Top 0.178: R7.P$2 2.21,46.63 3.07,45.77 3.07,43.56 2.44,42.93 2.39,42.93 ETH1.10
K2
  Top 0.178: R8.P$2 1.91,30.89 ETH1.12
LINKLED  (via drill 0.41)
  Top 0.178: v55.5,39.88 56.62,39.88 57.81,38.68 LINK.C | v54.18,43.92 53.54,44.55 52.2,44.55 51.83,44.18 | 51.83,44.18 51.64,43.99 51.64,42.82 47.65,42.82 45.92,44.55 42.47,44.55 37.52,39.6 37.52,38.88 37.07,38.56 v35.38,38.56 | v33.58,30.48 33.12,30.94 32.99,30.94 32.79,31.14 32.79,31.22 IC4.66 | 51.83,44.18 50.65,45.36 33.78,45.36 32.87,46.28 23.44,46.28 22.48,45.31 11.84,45.31 10.16,46.99 5.46,46.99 4.83,46.35 4.45,46.35 4.06,45.97 | 4.06,45.97 4.04,45.95 | R8.P$1 4.19,29.97 3.68,30.48 3.68,45.59 4.06,45.97
  Bottom 0.178: v55.5,39.88 54.18,41.07 v54.18,43.92 | v35.38,38.56 35.15,38.08 35.15,32.05 v33.58,30.48
MISO  (via drill 0.41)
  Top 0.178: v32.77,23.29 29.59,23.29 29.59,21.61 IC4.27
  Bottom 0.178: v32.77,23.29 32.77,32.74 33.22,33.2 33.22,47.9 31.83,49.3 J1.5
MOSI  (via drill 0.41)
  Top 0.178: v29.97,19.3 29.97,20.04 IC4.28 | v32.41,38.68 v35.15,41.43
  Bottom 0.178: v29.97,19.3 31.95,21.29 31.95,25.2 32.36,25.6 32.36,32.38 31.57,33.17 31.57,37.85 v32.41,38.68 | v35.15,41.43 35.15,48.51 34.37,49.3 J1.4
N$1
  Top 0.178: 7.62,3.17 PWR.A R1.P$2
N$2
  Top 0.178: L.A 24.94,43.13 26.01,42.06 26.04,42.06 R2.P$1
N$5  (via drill 0.41)
  Top 0.178: v46.56,37.77 46.63,37.85 50.19,37.85 100M.C | v46.56,32.77 41.91,32.77 41.27,32.13 39.75,30.66 34.92,30.66 33.93,29.67 33.22,29.67 32.38,30.5 32.38,31.22 IC4.67
  Bottom 0.178: v46.56,32.77 v46.56,37.77
N$6  (via drill 0.41)
  Top 0.178: v29.82,36.32 31.11,37.62 37.47,37.62 38.1,38.25 38.1,39.62 41.58,43.1 42.57,43.1 TX.C | v29.82,34.24 29.82,33.73 30.1,33.45 30.1,33.02 29.97,32.89 29.97,32.79 IC4.73
  Bottom 0.178: v29.82,34.24 v29.82,36.32
N$7  (via drill 0.41)
  Top 0.178: v32.41,45.39 32.79,45.01 49.45,45.01 50.19,44.27 RX.C | v30.33,30.48 30.33,31.06 30.38,31.11 30.38,31.22 IC4.72
  Bottom 0.178: v32.41,45.39 30.63,43.61 30.63,30.79 v30.33,30.48
N$8
  Top 0.178: COLL.C 42.19,38.09 41.3,37.26 35.31,37.26 32.74,34.7 31.88,34.7 30.79,33.6 30.79,32.79 IC4.71
N$9
  Top 0.178: TX.A 45.26,43.1 45.26,42.27 R12.P$2
N$10
  Top 0.178: C5.P$2 R4.P$2 R3.P$1
N$22
  Top 0.178: RX.A 52.88,43.1 52.88,42.27 R13.P$2
N$23
  Top 0.178: R14.P$2 45.34,35.94 45.25,36.03 COLL.A
N$24
  Top 0.178: FULLD.A 60.5,43.1 60.5,42.27 R15.P$2
N$25
  Top 0.178: 52.87,38.19 52.83,38.23 | 52.87,38.19 100M.A | R16.P$2 52.96,38.1 52.87,38.19
N$26
  Top 0.178: LINK.A 60.5,37.52 60.5,36.68 R17.P$2
N$29
  Top 0.178: R5.P$1 R6.P$2 C7.P$2
N$30
  Top 0.178: R10.P$2 R9.P$1
N$31
  Top 0.178: R10.P$1 23.95,36.98 23.37,36.4 23.37,31.57 24.28,30.66 24.87,30.2 IC4.1
OSC1E  (via drill 0.41)
  Top 0.178: R11.P$1 C13.P$2 36.83,43.08 36.83,41.22 Q2.2 | v34.75,29.31 30.33,29.31 29.13,30.5 28.8,30.81 28.8,31.22 IC4.76
  Bottom 0.178: v34.75,29.31 36.32,30.89 36.32,39.04 Q2.2
OSC2E  (via drill 0.41)
  Top 0.178: R11.P$2 C14.P$2 31.24,43.08 31.24,41.22 Q2.1 31.24,39.04 v29.82,37.62 | v27.79,33.53 28.19,33.12 28.99,33.12 29.18,32.93 29.18,32.79 IC4.75
  Bottom 0.178: v27.79,33.53 27.79,35.59 v29.82,37.62
PD2
  Top 0.178: INT.2 62.69,43.2 58.75,47.14 58.75,49.3 J3.3
RESET  (via drill 0.41)
  Top 0.178: S1.4 14.4,5.89 21.16,5.89 21.26,5.79 21.31,5.79 23.47,3.63 32.28,3.63 POWER.1 | v38.15,29.82 37.36,29.82 IC4.59
  Bottom 0.178: v38.15,29.82 37.69,29.36 37.69,27.53 35.56,25.4 35.59,15.95 32.56,13.01 29.36,13.01 29.36,7.37 32.69,4.04 POWER.1 | 12.7,5.87 S1.4 | S1.3 12.7,5.87 | 12.7,5.87 12.7,5.71
RXIN  (1 unrouted)
  Top 0.178: 19.07,33.83 16.92,35.99 15.75,35.99 ETH1.6 | IC4.6 24.61,28.22 24.28,28.22 20.22,32.28 20.22,33.12 19.68,33.66 R5.P$2
RXIP
  Top 0.178: ETH1.4 15.75,38.53 16.41,38.53 19.07,35.87 R6.P$1 20.83,34.42 20.83,32.26 24.47,28.62 IC4.5
SCK  (via drill 0.41)
  Top 0.178: v23.24,42.6 23.27,42.6 23.77,42.09 R2.P$2 24.66,41.15 24.69,41.15 v25.2,40.64 | v28.75,19.3 29.57,18.49 30.79,18.49 30.79,20.04 IC4.30
  Bottom 0.178: v23.24,42.6 24.84,44.2 28.22,44.2 28.22,49.71 J1.6 | v28.75,19.3 28.75,23.14 24.69,27.2 24.69,33.88 24.59,33.98 24.59,40.03 v25.2,40.64
SEN  (via drill 0.41)
  Top 0.178: IC4.31 31.19,20.04 31.19,17.88 R18.P$2 31.27,17.22 31.83,16.89 v32.31,16.38
  Bottom 0.178: PROG.2 18.16,7.16 20.68,7.16 22.02,7.16 25.53,10.67 25.53,12.19 27.81,14.48 30.48,14.48 32.31,16.31 v32.31,16.38
SH  (via drill 0.41)
  Top 0.178: v9.14,49.05 9.37,49.05 10.67,47.75 19.15,47.78 L1.2 | ETH1.S2 9.22,31.37 9.22,44.98 ETH1.S1
  Bottom 0.178: v9.14,49.05 9.14,46.25 ETH1.S1
SS  (via drill 0.41)
  Top 0.178: v30.4,22.48 30.4,21.61 IC4.29 | v31.55,25.96 31.9,26.31 v34.49,26.31
  Bottom 0.178: v30.4,22.48 31.55,23.62 v31.55,25.96 | v34.49,26.31 37.34,29.16 37.34,39.17 37.39,39.22 37.39,48.82 36.91,49.3 J1.3
TXON
  Top 0.178: IC4.9 24.35,27.02 24.23,26.9 22.39,26.89 18.8,30.48 14.22,30.48 10.67,34.04 10.67,38.1 12.65,40.08 | 12.65,40.08 12.7,40.13 | 12.65,40.08 ETH1.3 12.5,40.08 11.43,41.15 11.43,43.94 11.68,44.2 14.22,44.2 14.73,43.69 R3.P$2
TXOP
  Top 0.178: IC4.8 25.35,27.41 23.98,27.41 23.88,27.3 22.73,27.3 22.61,27.43 22.63,27.41 19.05,30.99 14.48,30.99 11.18,34.29 11.18,37.85 12.19,38.86 12.95,38.86 13.72,39.62 13.72,41.4 12.52,42.59 ETH1.1 12.5,42.62 11.94,43.18 11.94,43.43 12.19,43.69 13.72,43.69 14.22,43.18 18.29,43.18 19.68,41.78 R4.P$1
WP  (via drill 0.41)
  Top 0.178: v27.48,11.1 28.22,11.1 R20.P$1 | v27.91,7.42 28.65,7.42 WP.1 29.77,6.33 30.07,6.02 39.78,6.02 v39.83,6.07 | J2.1 50.06,3.63 46.79,6.91 45.44,6.91 X1.WRITE_PROT 42.01,6.88 v41.45,6.33
  Bottom 0.178: v27.48,11.1 27.91,10.67 v27.91,7.42 | v39.83,6.07 41.45,6.07 v41.45,6.33

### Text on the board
Top: LC
Bottom: LS
tNames: 3 2 1 0 9 8 | 7 6 5 4 3 2 1 0 | TX | RX | GND | 1 1 1 1 | * | * | * | AREF | * | * | * | RESET | 3V3 | ANALOG IN | 5V Gnd 9V | A0 1 2 3 4 A5
bNames: Made in | Italy | designed by | tinker.it
Reference: R7 | R3 | C14 | R11 | C13 | R4 | R2 | R12 | R13 | R15 | Q2 | C5 | R9 | C7 | R10 | R14 | R16 | R17 | R6 | C4 | R5 | R8 | IC1 | C1 | C3 | R18 | C16 | C18 | C15 | C17 | R19 | R20 | C12 | C6 | R1 | X2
